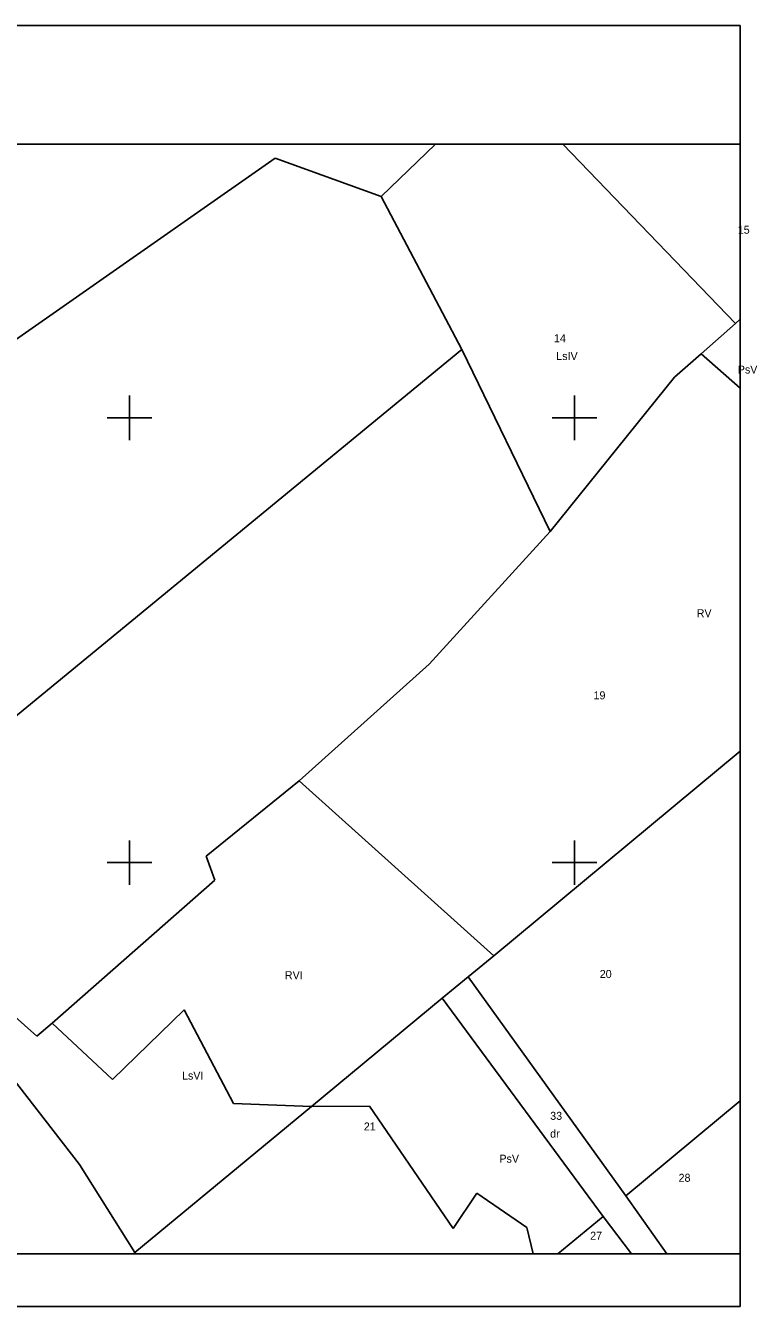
# Model space of a CAD drawing. Extents: x 4650326 to 4650741, y 5341000 to 5341288.
# Drawn here: x 4650576.7 to 4650741.1, y 5341000.2 to 5341288.2 of the extents above; entities that cross this region are included whole.
import ezdxf

# ---------------------------------------------------------------- set-up
doc = ezdxf.new("R2010")
doc.units = 0
for name, color, linetype in [('Warstwa 1', 7, 'Continuous'), ('Warstwa 24', 7, 'Continuous'), ('Warstwa 25', 7, 'Continuous'), ('Warstwa 26', 7, 'Continuous'), ('Warstwa 27', 7, 'Continuous'), ('Warstwa 48', 7, 'Continuous'), ('Warstwa 60', 7, 'Continuous')]:
    doc.layers.add(name, color=color, linetype=linetype)

msp = doc.modelspace()

# ---------------------------------------------------------------- linework, layer by layer
at = {"layer": 'Warstwa 1'}
msp.add_lwpolyline([(4650326.19, 5341261.537), (4650737.19, 5341261.537), (4650737.19, 5341288.203), (4650326.19, 5341288.203)], close=True, dxfattribs=at)
at = {"layer": 'Warstwa 25'}
for p, q in [((4650668.731, 5341261.537), (4650656.58, 5341249.79)), ((4650668.731, 5341261.537), (4650656.58, 5341249.79)), ((4650736.17, 5341221.25), (4650697.405, 5341261.537)), ((4650632.75, 5341258.37), (4650570.57, 5341214.93)), ((4650632.75, 5341258.37), (4650570.57, 5341214.93)), ((4650656.58, 5341249.79), (4650632.75, 5341258.37)), ((4650656.58, 5341249.79), (4650632.75, 5341258.37)), ((4650674.68, 5341215.41), (4650656.58, 5341249.79)), ((4650674.68, 5341215.41), (4650656.58, 5341249.79)), ((4650737.19, 5341222.192), (4650736.17, 5341221.25)), ((4650737.19, 5341222.192), (4650736.17, 5341221.25)), ((4650736.17, 5341221.25), (4650728.42, 5341214.41)), ((4650736.17, 5341221.25), (4650728.42, 5341214.41)), ((4650674.68, 5341215.41), (4650534.87, 5341100.4)), ((4650694.55, 5341174.45), (4650674.68, 5341215.41)), ((4650694.55, 5341174.45), (4650674.68, 5341215.41)), ((4650728.42, 5341214.41), (4650722.43, 5341209.13)), ((4650728.42, 5341214.41), (4650722.43, 5341209.13)), ((4650722.43, 5341209.13), (4650694.55, 5341174.45)), ((4650722.43, 5341209.13), (4650694.55, 5341174.45)), ((4650737.19, 5341125.066), (4650681.88, 5341079.06)), ((4650737.19, 5341125.066), (4650681.88, 5341079.06)), ((4650681.88, 5341079.06), (4650676.14, 5341074.29)), ((4650681.88, 5341079.06), (4650676.14, 5341074.29)), ((4650676.14, 5341074.29), (4650670.27, 5341069.52)), ((4650676.14, 5341074.29), (4650670.27, 5341069.52)), ((4650711.56, 5341025.03), (4650676.14, 5341074.29)), ((4650711.56, 5341025.03), (4650676.14, 5341074.29)), ((4650670.27, 5341069.52), (4650640.88, 5341045.16)), ((4650670.27, 5341069.52), (4650640.88, 5341045.16)), ((4650706.42, 5341020.38), (4650670.27, 5341069.52)), ((4650706.42, 5341020.38), (4650670.27, 5341069.52)), ((4650737.19, 5341046.442), (4650711.56, 5341025.03)), ((4650640.88, 5341045.16), (4650601.24, 5341012.29)), ((4650720.774, 5341012.003), (4650711.56, 5341025.03)), ((4650720.774, 5341012.003), (4650711.56, 5341025.03)), ((4650706.42, 5341020.38), (4650696.23, 5341012.003)), ((4650712.792, 5341012.003), (4650706.42, 5341020.38)), ((4650712.792, 5341012.003), (4650706.42, 5341020.38)), ((4650601.24, 5341012.29), (4650600.894, 5341012.003))]:
    msp.add_line(p, q, dxfattribs=at)
at = {"layer": 'Warstwa 27'}
for p, q in [((4650656.58, 5341249.79), (4650668.731, 5341261.537)), ((4650656.58, 5341249.79), (4650668.731, 5341261.537)), ((4650570.57, 5341214.93), (4650632.75, 5341258.37)), ((4650570.57, 5341214.93), (4650632.75, 5341258.37)), ((4650632.75, 5341258.37), (4650656.58, 5341249.79)), ((4650632.75, 5341258.37), (4650656.58, 5341249.79)), ((4650656.58, 5341249.79), (4650674.68, 5341215.41)), ((4650656.58, 5341249.79), (4650674.68, 5341215.41)), ((4650736.17, 5341221.25), (4650737.19, 5341222.192)), ((4650736.17, 5341221.25), (4650737.19, 5341222.192)), ((4650728.42, 5341214.41), (4650736.17, 5341221.25)), ((4650728.42, 5341214.41), (4650736.17, 5341221.25)), ((4650674.68, 5341215.41), (4650694.55, 5341174.45)), ((4650674.68, 5341215.41), (4650694.55, 5341174.45)), ((4650722.43, 5341209.13), (4650728.42, 5341214.41)), ((4650722.43, 5341209.13), (4650728.42, 5341214.41)), ((4650728.42, 5341214.41), (4650737.19, 5341206.685)), ((4650694.55, 5341174.45), (4650722.43, 5341209.13)), ((4650694.55, 5341174.45), (4650722.43, 5341209.13)), ((4650667.35, 5341144.65), (4650694.55, 5341174.45)), ((4650638.1, 5341118.36), (4650667.35, 5341144.65)), ((4650681.88, 5341079.06), (4650737.19, 5341125.066)), ((4650681.88, 5341079.06), (4650737.19, 5341125.066)), ((4650617.24, 5341101.45), (4650638.1, 5341118.36)), ((4650638.1, 5341118.36), (4650681.88, 5341079.06)), ((4650617.24, 5341101.45), (4650619.18, 5341096.02)), ((4650534.87, 5341100.4), (4650579.17, 5341060.96)), ((4650582.61, 5341063.88), (4650619.18, 5341096.02)), ((4650676.14, 5341074.29), (4650681.88, 5341079.06)), ((4650676.14, 5341074.29), (4650681.88, 5341079.06)), ((4650670.27, 5341069.52), (4650676.14, 5341074.29)), ((4650670.27, 5341069.52), (4650676.14, 5341074.29)), ((4650676.14, 5341074.29), (4650711.56, 5341025.03)), ((4650676.14, 5341074.29), (4650711.56, 5341025.03)), ((4650640.88, 5341045.16), (4650670.27, 5341069.52)), ((4650640.88, 5341045.16), (4650670.27, 5341069.52)), ((4650670.27, 5341069.52), (4650706.42, 5341020.38)), ((4650670.27, 5341069.52), (4650706.42, 5341020.38)), ((4650596.16, 5341051.2), (4650612.31, 5341066.88)), ((4650612.31, 5341066.88), (4650623.38, 5341045.83)), ((4650579.17, 5341060.96), (4650582.61, 5341063.88)), ((4650582.61, 5341063.88), (4650596.16, 5341051.2)), ((4650571.05, 5341055.04), (4650588.74, 5341032.12)), ((4650623.38, 5341045.83), (4650640.88, 5341045.16)), ((4650640.88, 5341045.16), (4650653.91, 5341045.19)), ((4650653.91, 5341045.19), (4650672.72, 5341017.71)), ((4650588.74, 5341032.12), (4650601.24, 5341012.29)), ((4650672.72, 5341017.71), (4650678.03, 5341025.65)), ((4650678.03, 5341025.65), (4650689.31, 5341017.92)), ((4650711.56, 5341025.03), (4650720.774, 5341012.003)), ((4650711.56, 5341025.03), (4650720.774, 5341012.003)), ((4650689.31, 5341017.92), (4650690.733, 5341012.003)), ((4650706.42, 5341020.38), (4650712.792, 5341012.003)), ((4650706.42, 5341020.38), (4650712.792, 5341012.003)), ((4650601.24, 5341012.29), (4650601.432, 5341012.003))]:
    msp.add_line(p, q, dxfattribs=at)
at = {"layer": 'Warstwa 48'}
for points in [[(4650326.19, 5341000.203), (4650737.19, 5341000.203), (4650737.19, 5341288.203), (4650326.19, 5341288.203)], [(4650326.19, 5341012.003), (4650737.19, 5341012.003), (4650737.19, 5341261.537), (4650326.19, 5341261.537)]]:
    msp.add_lwpolyline(points, close=True, dxfattribs=at)
at = {"layer": 'Warstwa 60'}
for p, q in [((4650600, 5341195), (4650600, 5341205)), ((4650600, 5341195), (4650600, 5341205)), ((4650700, 5341195), (4650700, 5341205)), ((4650700, 5341195), (4650700, 5341205)), ((4650595, 5341200), (4650605, 5341200)), ((4650595, 5341200), (4650605, 5341200)), ((4650695, 5341200), (4650705, 5341200)), ((4650695, 5341200), (4650705, 5341200)), ((4650600, 5341095), (4650600, 5341105)), ((4650600, 5341095), (4650600, 5341105)), ((4650700, 5341095), (4650700, 5341105)), ((4650700, 5341095), (4650700, 5341105)), ((4650595, 5341100), (4650605, 5341100)), ((4650595, 5341100), (4650605, 5341100)), ((4650695, 5341100), (4650705, 5341100)), ((4650695, 5341100), (4650705, 5341100))]:
    msp.add_line(p, q, dxfattribs=at)

# ---------------------------------------------------------------- texts
at = {"layer": 'Warstwa 24'}
for s, p in [('15', (4650736.68, 5341241.4)), ('14', (4650695.38, 5341217)), ('19', (4650704.27, 5341136.7)), ('20', (4650705.67, 5341074.05)), ('33', (4650694.53, 5341042.15)), ('21', (4650652.66, 5341039.76)), ('28', (4650723.38, 5341028.22)), ('27', (4650703.51, 5341015.19))]:
    msp.add_text(s, height=1.8, dxfattribs=at).set_placement(p)
at = {"layer": 'Warstwa 26'}
for s, p in [('LsIV', (4650695.89, 5341213)), ('PsV', (4650736.68, 5341209.97)), ('RV', (4650727.45, 5341155.18)), ('RVI', (4650634.92, 5341073.77)), ('LsVI', (4650611.8, 5341051.2)), ('dr', (4650694.53, 5341038.15)), ('PsV', (4650683.12, 5341032.52))]:
    msp.add_text(s, height=1.8, dxfattribs=at).set_placement(p)

doc.saveas('drawing.dxf')
